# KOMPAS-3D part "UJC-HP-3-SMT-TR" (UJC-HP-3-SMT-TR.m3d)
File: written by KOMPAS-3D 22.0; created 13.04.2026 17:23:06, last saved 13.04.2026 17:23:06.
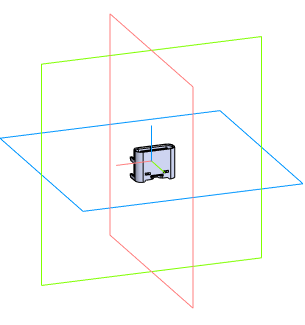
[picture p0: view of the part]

Document properties: Автор: Andrey; Полное имя файла: C:\Users\User1\Documents\UJC-HP-3-SMT-TR.m3d

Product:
- Part/product: UJC-HP-3-SMT-TR

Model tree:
1. Операция без истории:1
2. Операция без истории:2
3. Операция без истории:3
4. Операция без истории:4
5. Операция без истории:5
6. Операция без истории:6
7. Операция без истории:7
8. Операция без истории:8
9. Операция без истории:9
10. Операция без истории:10
11. Операция без истории:11
12. Операция без истории:12
13. Операция без истории:13
14. Поверхность без истории:1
